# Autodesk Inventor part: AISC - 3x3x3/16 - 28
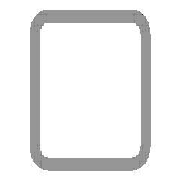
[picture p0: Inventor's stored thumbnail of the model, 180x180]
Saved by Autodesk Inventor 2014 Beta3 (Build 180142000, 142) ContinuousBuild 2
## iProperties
IsCustomPart: 1
Created: 2011-01
Part Number: AISC - 3x3x3/16 - 28
Material: Steel, Mild
Description: Tube
Document SubType Name: Modeling
Standard: ANSI
Designer: Beta-8540w
Standards Organization: ANSI
Language: en-US
Size Designation: 3x3x3/16
Categories: <MemberInstance><Categories><Category DisplayName="Structural Shapes" InternalName="089c4875-fa83-4c05-b084-43b9cc11f5ed" Mnemonic="GRDR"><CategoryParameter Dis
Stock Number: 3x3x3/16
Density: 7.86 g/cm^3
Appearance: Steel
G_L: 28.000 in
G_W: 3.000 in
G_H: 3.000 in
_CCFamilyMember: 9
_CCFamilyDisplayName: ANSI AISC (Square) - Tube
_FrameMemberDoc: Frame Member File
_Version: 15.0.0
_GetPNFromCC: 1
Author: Beta-8540w
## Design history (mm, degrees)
node "Start plane"
node "End plane"
sketch "Sketch"
  geometry: L1 (-38.1, -28.575)-(-38.1, 28.575); L2 (-28.575, 38.1)-(28.575, 38.1); L3 (38.1, 28.575)-(38.1, -28.575); L4 (28.575, -38.1)-(-28.575, -38.1); L5 (-28.575, 33.337)-(28.575, 33.338); L6 (33.338, 28.575)-(33.338, -28.575); L7 (28.575, -33.337)-(-28.575, -33.338); L8 (-33.338, -28.575)-(-33.338, 28.575); L9 (0, 56.102)-(0, -56.102) reference; L10 (-56.102, 0)-(56.102, 0) reference; A1 r 9.525 centre (-28.575, -28.575) between (-38.1, -28.575) and (-28.575, -38.1); A2 r 9.525 centre (-28.575, 28.575) between (-28.575, 38.1) and (-38.1, 28.575); A3 r 9.525 centre (28.575, 28.575) between (38.1, 28.575) and (28.575, 38.1); A4 r 9.525 centre (28.575, -28.575) between (28.575, -38.1) and (38.1, -28.575); A5 r 4.763 centre (-28.575, 28.575) between (-28.575, 33.337) and (-33.338, 28.575); A6 r 4.763 centre (28.575, 28.575) between (33.338, 28.575) and (28.575, 33.338); A7 r 4.763 centre (28.575, -28.575) between (28.575, -33.337) and (33.338, -28.575); A8 r 4.763 centre (-28.575, -28.575) between (-33.338, -28.575) and (-28.575, -33.338)
  constraints: 16 end point, 16 point on circle, 8 centre point, 8 tangent, 4 parallel, 3 equal radius, 2 perpendicular, 7 other
  dimensions: "d10" = 76.2 distance between parallel lines of L2 L4 (= G_H); "d11" = 76.2 distance between parallel lines of L1 L3 (= G_W); "d12" = 4.7625 distance between parallel lines of L3 L6 (= G_T); "d15" = 38.1 distance between parallel lines of L2 L10 (= 0.5 x d10); "d16" = 38.1 distance between parallel lines of L9 L3 (= 0.5 x d11); "d17" = 9.525 radius of A1 (= G_IR)
extrude "Body" new body sketch "Sketch" stored distance "d3" = 711.2 (= G_L); taper "d4" = 0 deg
node "Driven Length"
  sketch "Sketch3"
    geometry: L1 (0, 0)-(10, 0) reference
    constraints: 2 end point, 1 horizontal
  workplane "Work Plane3"
  sketch "Sketch4"
    geometry: L1 (-2, 0)-(12, 0) reference; L2 (-2, 711.2)-(12, 711.2) reference
    dimensions: "d19" = 711.2 distance between parallel lines of L1 L2 (derived)
body "Solid1"
other parameters: "G_W" = 76.2 [user parameter; used in 1 equation term], "G_H" = 76.2 [user parameter; used in 1 equation term], "G_T" = 4.7625 [user parameter; used in 1 equation term], "G_IR" = 9.525 [user parameter; used in 1 equation term], "G_L" = 711.2 (= d19) [user parameter; used in 1 equation term], "G_OFFSET_START" = 0 [user parameter; used in 1 equation term], "G_OFFSET_END" = 0 [user parameter; used in 1 equation term], "d13" = 0 (computed from G_OFFSET_START), "d14" = 711.2 (= G_OFFSET_END + B_L), "B_L" = 711.2 [user parameter; used in 1 equation term], "d18" = 90 deg
